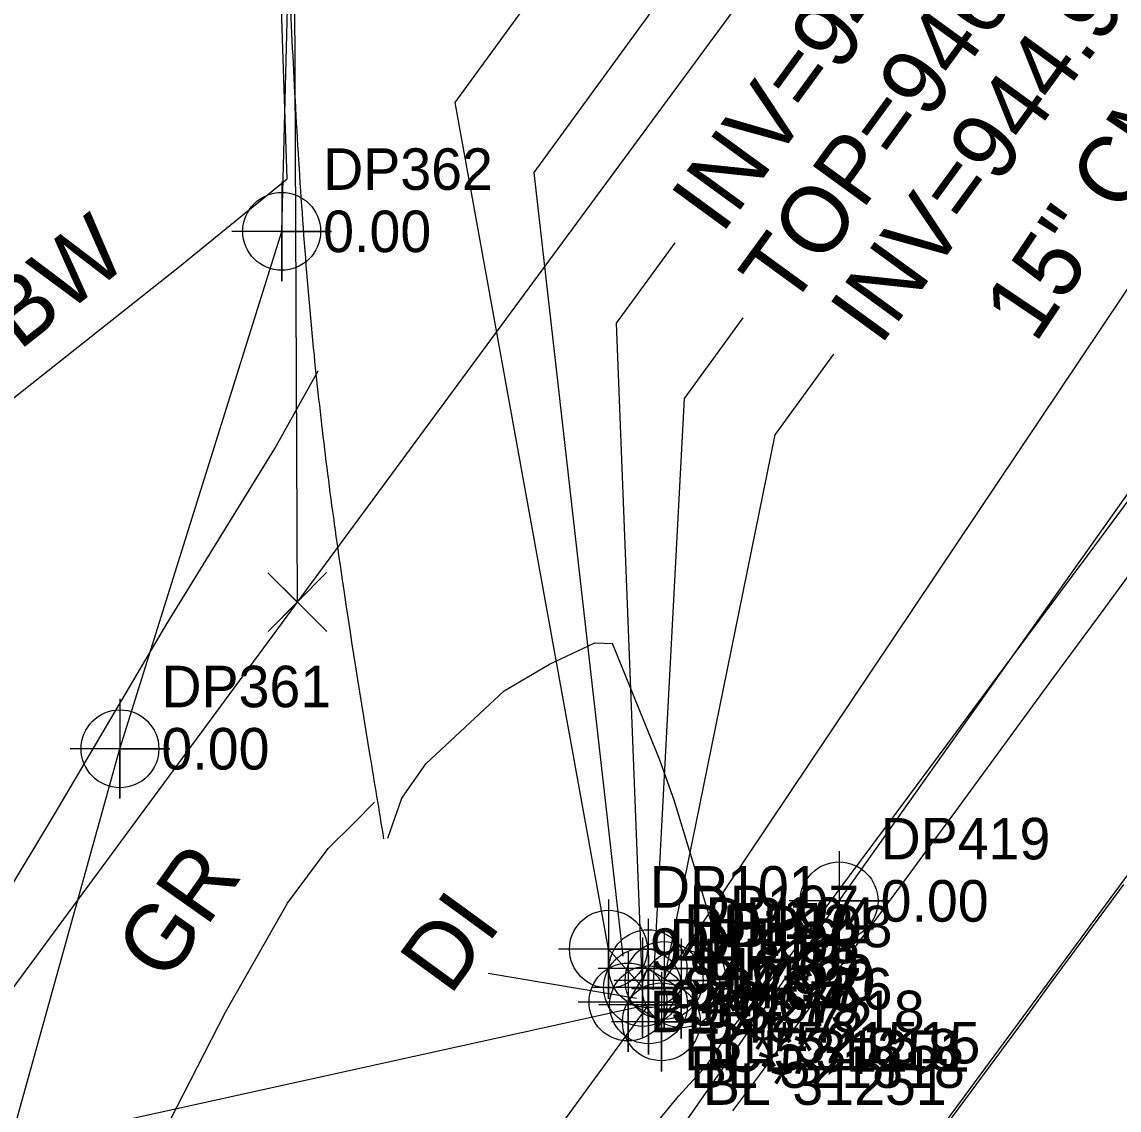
# Model space of a CAD drawing. Extents: x 1182322 to 1186765, y 572295 to 575411.
# Drawn here: x 1183866.3 to 1183932.4, y 573218.4 to 573283.9 of the extents above; entities that cross this region are included whole.
import ezdxf

# ---------------------------------------------------------------- set-up
doc = ezdxf.new("R2010")
doc.units = 0
for name, color, linetype in [('COGO Default Chain', 7, 'Continuous'), ('Exist Horizontal Alignment', 7, 'Continuous'), ('Exist Other Culture Fence Line', 7, 'Continuous'), ('Exist Other Culture Fence Line Text', 7, 'Continuous'), ('Exist Property Corner CELL', 7, 'Continuous'), ('Exist Property Line', 7, 'Continuous'), ('Exist Right of Way Line', 7, 'Continuous'), ('Exist Roads EOP', 7, 'Continuous'), ('Exist Roads EOP Other', 7, 'Continuous'), ('Exist Roads EOT', 7, 'Continuous'), ('Exist Roads Soil', 7, 'Continuous'), ('Exist Roads Soil Text', 7, 'Continuous'), ('Exist Structure Minor Drop Inlet', 7, 'Continuous'), ('Exist Structure Minor Drop Inlet Cogo Comment', 7, 'Continuous'), ('Exist Structure Minor Drop Inlet Cogo Elevation', 7, 'Continuous'), ('Exist Structure Minor Drop Inlet Cogo Number', 7, 'Continuous'), ('Exist Structure Minor Drop Inlet Cogo Point CELL', 7, 'Continuous'), ('Exist Structure Minor Drop Inlet Leader', 7, 'Continuous'), ('Exist Structure Minor Drop Inlet Text', 7, 'Continuous'), ('Exist Structure Minor Drop Inlet Top Elevation', 7, 'Continuous'), ('Exist Structure Minor Pipes CMP 15 Inch', 7, 'Continuous'), ('Exist Structure Minor Pipes CMP 15 Inch Cogo Comment', 7, 'Continuous'), ('Exist Structure Minor Pipes CMP 15 Inch Cogo Elevation', 7, 'Continuous'), ('Exist Structure Minor Pipes CMP 15 Inch Cogo Number', 7, 'Continuous'), ('Exist Structure Minor Pipes CMP 15 Inch Cogo Point CELL', 7, 'Continuous'), ('Exist Structure Minor Pipes CMP 15 Inch Invert', 7, 'Continuous'), ('Exist Structure Minor Pipes CMP 15 Inch Text', 7, 'Continuous'), ('Exist Structure Minor Pipes CMP 18 Inch', 7, 'Continuous'), ('Exist Structure Minor Pipes CMP 18 Inch Cogo Comment', 7, 'Continuous'), ('Exist Structure Minor Pipes CMP 18 Inch Cogo Elevation', 7, 'Continuous'), ('Exist Structure Minor Pipes CMP 18 Inch Cogo Number', 7, 'Continuous'), ('Exist Structure Minor Pipes CMP 18 Inch Cogo Point CELL', 7, 'Continuous'), ('Exist Structure Minor Pipes CMP 18 Inch Invert', 7, 'Continuous'), ('Exist Structure Minor Pipes CMP 18 Inch Leader', 7, 'Continuous'), ('Exist Utilities Telephone UG Cable SUE LOS C', 7, 'Continuous'), ('Exist Utilities Telephone UG Cable SUE LOS C Cogo Elevation', 7, 'Continuous'), ('Exist Utilities Telephone UG Cable SUE LOS C Cogo Number', 7, 'Continuous'), ('Exist Utilities Telephone UG Cable SUE LOS C Cogo Point CELL', 7, 'Continuous'), ('Exist Utilities Telephone UG FO SUE LOS C', 7, 'Continuous'), ('Exist Utilities Telephone UG FO SUE LOS C Cogo Elevation', 7, 'Continuous'), ('Exist Utilities Telephone UG FO SUE LOS C Cogo Number', 7, 'Continuous'), ('Exist Utilities Telephone UG FO SUE LOS C Cogo Point CELL', 7, 'Continuous')]:
    doc.layers.add(name, color=color, linetype=linetype)

msp = doc.modelspace()

# ---------------------------------------------------------------- linework, layer by layer
at = {"layer": 'COGO Default Chain'}
msp.add_line((1183822.39, 573082.624), (1183960.792, 573270.412), dxfattribs=at)
at = {"layer": 'Exist Horizontal Alignment'}
msp.add_line((1183822.39, 573082.624), (1183960.792, 573270.412), dxfattribs=at)
at = {"layer": 'Exist Other Culture Fence Line'}
for points in [[(1183875.706, 573269.13), (1183882.281, 573274.5), (1183880.264, 573335.479), (1183879.942, 573365.545), (1183879.147, 573405.433), (1183879.443, 573440.932), (1183879.29, 573466.248), (1183879.454, 573496.478), (1183879.147, 573519.038), (1183879.392, 573536.929)], [(1183822.128, 573226.748), (1183822.325, 573226.605), (1183840.399, 573241.182), (1183875.706, 573269.13)]]:
    msp.add_lwpolyline(points, dxfattribs=at)
at = {"layer": 'Exist Property Corner CELL'}
msp.add_line((1183882.9, 573249.002), (1183882.9, 573249.002), dxfattribs=at)
msp.add_lwpolyline([(1183884.675, 573247.242), (1183881.124, 573250.762), (1183882.9, 573249.002), (1183881.14, 573247.226), (1183884.66, 573250.777)], dxfattribs=at)
at = {"layer": 'Exist Property Line'}
msp.add_line((1183882.9, 573249.002), (1183880.082, 573905.178), dxfattribs=at)
at = {"layer": 'Exist Right of Way Line'}
msp.add_line((1183782.141, 573112.288), (1183920.542, 573300.076), dxfattribs=at)
at = {"layer": 'Exist Roads EOP'}
for points in [[(1183909.008, 573223.249), (1183912.581, 573227.696), (1183916.155, 573232.509), (1183919.729, 573237.324), (1183923.303, 573242.139), (1183926.878, 573246.955), (1183930.453, 573251.77), (1183934.028, 573256.586), (1183937.602, 573261.401), (1183941.177, 573266.216), (1183944.753, 573271.031), (1183948.329, 573275.845), (1183951.903, 573280.659), (1183955.478, 573285.472), (1183959.053, 573290.286), (1183962.587, 573295.131), (1183965.957, 573300.091), (1183969.392, 573305.007), (1183972.931, 573309.849), (1183975.448, 573313.161)], [(1183907.64, 573230.343), (1183905.584, 573237.076), (1183904.715, 573239.546), (1183903.781, 573241.808), (1183901.869, 573246.517)], [(1183896.313, 573204.685), (1183897.787, 573206.702), (1183899.179, 573208.776), (1183900.543, 573210.869), (1183901.682, 573213.094), (1183902.796, 573215.329), (1183904.285, 573217.335), (1183905.87, 573219.264), (1183907.547, 573221.115), (1183908.955, 573223.183), (1183908.94, 573225.671), (1183908.356, 573228.021), (1183907.646, 573230.325)]]:
    msp.add_lwpolyline(points, dxfattribs=at)
msp.add_spline([(1183888.111, 573234.75), (1183887.266, 573239.862), (1183885.398, 573251.839), (1183884.594, 573257.847), (1183883.92, 573263.875), (1183882.827, 573278.308), (1183882.139, 573292.763), (1183881.535, 573306.754), (1183881.086, 573320.75), (1183880.571, 573351.991), (1183880.026, 573376.469)], degree=3, dxfattribs=at)
at = {"layer": 'Exist Roads EOP Other'}
msp.add_lwpolyline([(1183888.336, 573234.788), (1183889.189, 573237.205), (1183890.64, 573239.26), (1183895.356, 573243.663), (1183898.082, 573245.264), (1183900.819, 573246.558), (1183901.869, 573246.517)], dxfattribs=at)
at = {"layer": 'Exist Roads EOT'}
for points in [[(1183909.126, 573218.371), (1183910.622, 573220.373), (1183912.117, 573222.374), (1183913.611, 573224.375), (1183915.107, 573226.377), (1183916.602, 573228.378), (1183918.097, 573230.38), (1183919.589, 573232.386), (1183921.066, 573234.399), (1183922.544, 573236.415), (1183924.021, 573238.43), (1183925.498, 573240.446), (1183926.977, 573242.46), (1183928.457, 573244.474), (1183929.938, 573246.487), (1183931.418, 573248.5), (1183932.898, 573250.514)], [(1183922.291, 573217.923), (1183923.777, 573219.931), (1183925.261, 573221.942), (1183926.741, 573223.954), (1183928.222, 573225.967), (1183929.703, 573227.98), (1183931.184, 573229.993), (1183932.664, 573232.006)]]:
    msp.add_lwpolyline(points, dxfattribs=at)
at = {"layer": 'Exist Roads Soil'}
for points in [[(1183755.873, 573330.816), (1183765.138, 573309.872), (1183771.686, 573295.329), (1183780.035, 573281.755), (1183791.891, 573260.841), (1183800.45, 573245.847), (1183810.819, 573229.111), (1183816.525, 573221.117), (1183823.782, 573213.839), (1183828.634, 573210.3), (1183831.855, 573208.707), (1183837.122, 573206.804), (1183840.935, 573206.353), (1183842.977, 573206.546), (1183844.891, 573206.932), (1183846.712, 573207.652), (1183848.009, 573208.384), (1183849.32, 573209.506), (1183856.494, 573218.373), (1183862.168, 573226.089), (1183868.28, 573236.258), (1183875.04, 573247.694), (1183881.535, 573258.254), (1183884.151, 573262.938)], [(1183893.801, 573201.366), (1183889.036, 573197.634), (1183886.486, 573196.138), (1183879.339, 573192.758), (1183875.323, 573191.588), (1183870.883, 573191.124), (1183867.11, 573191.214), (1183865.739, 573191.904), (1183864.44, 573193.109), (1183864.328, 573193.924), (1183864.577, 573195.747), (1183866.17, 573198.968), (1183873.534, 573214.473), (1183878.575, 573224.315), (1183882.305, 573230.864), (1183884.757, 573234.166), (1183886.379, 573235.764), (1183887.543, 573236.959)]]:
    msp.add_lwpolyline(points, dxfattribs=at)
at = {"layer": 'Exist Structure Minor Drop Inlet'}
msp.add_lwpolyline([(1183904.82, 573223.726), (1183902.81, 573224.92), (1183904.015, 573226.93), (1183906.014, 573225.717), (1183904.82, 573223.726)], dxfattribs=at)
at = {"layer": 'Exist Structure Minor Drop Inlet Cogo Point CELL'}
for points in [[(1183904.015, 573229.93), (1183904.015, 573223.93), (1183904.015, 573226.93), (1183907.015, 573226.93), (1183901.015, 573226.93)], [(1183906.014, 573228.717), (1183906.014, 573222.717), (1183906.014, 573225.717), (1183909.014, 573225.717), (1183903.014, 573225.717)], [(1183902.81, 573227.92), (1183902.81, 573221.92), (1183902.81, 573224.92), (1183905.81, 573224.92), (1183899.81, 573224.92)], [(1183904.82, 573226.726), (1183904.82, 573220.726), (1183904.82, 573223.726), (1183907.82, 573223.726), (1183901.82, 573223.726)]]:
    msp.add_lwpolyline(points, dxfattribs=at)
for centre in [(1183904.015, 573226.93), (1183906.014, 573225.717), (1183902.81, 573224.92), (1183904.82, 573223.726)]:
    msp.add_circle(centre, 2.344, dxfattribs=at)
at = {"layer": 'Exist Structure Minor Drop Inlet Leader'}
msp.add_line((1183903.311, 573225.13), (1183894.39, 573226.64), dxfattribs=at)
at = {"layer": 'Exist Structure Minor Pipes CMP 15 Inch'}
msp.add_line((1183904.982, 573226.217), (1183966.819, 573318.499), dxfattribs=at)
at = {"layer": 'Exist Structure Minor Pipes CMP 15 Inch Cogo Point CELL'}
msp.add_lwpolyline([(1183904.982, 573229.217), (1183904.982, 573223.217), (1183904.982, 573226.217), (1183907.982, 573226.217), (1183901.982, 573226.217)], dxfattribs=at)
msp.add_circle((1183904.982, 573226.217), 2.344, dxfattribs=at)
at = {"layer": 'Exist Structure Minor Pipes CMP 18 Inch'}
for p, q in [((1183901.63, 573228.102), (1183903.684, 573225.798)), ((1183904.046, 573224.75), (1183807.68, 573092.895))]:
    msp.add_line(p, q, dxfattribs=at)
at = {"layer": 'Exist Structure Minor Pipes CMP 18 Inch Cogo Point CELL'}
for points in [[(1183901.63, 573231.102), (1183901.63, 573225.102), (1183901.63, 573228.102), (1183904.63, 573228.102), (1183898.63, 573228.102)], [(1183903.684, 573228.798), (1183903.684, 573222.798), (1183903.684, 573225.798), (1183906.684, 573225.798), (1183900.684, 573225.798)], [(1183904.046, 573227.75), (1183904.046, 573221.75), (1183904.046, 573224.75), (1183907.046, 573224.75), (1183901.046, 573224.75)]]:
    msp.add_lwpolyline(points, dxfattribs=at)
for centre in [(1183901.63, 573228.102), (1183903.684, 573225.798), (1183904.046, 573224.75)]:
    msp.add_circle(centre, 2.344, dxfattribs=at)
at = {"layer": 'Exist Structure Minor Pipes CMP 18 Inch Invert'}
for points in [[(1183902.516, 573227.677), (1183897.149, 573274.868), (1183912.997, 573296.612)], [(1183901.63, 573228.102), (1183892.395, 573279.102), (1183904.279, 573295.408)], [(1183903.684, 573225.798), (1183902.113, 573265.795), (1183905.647, 573270.644)], [(1183904.315, 573225.644), (1183906.215, 573261.271), (1183909.748, 573266.12)], [(1183904.982, 573226.217), (1183911.664, 573259.079), (1183915.198, 573263.928)]]:
    msp.add_lwpolyline(points, dxfattribs=at)
at = {"layer": 'Exist Structure Minor Pipes CMP 18 Inch Leader'}
msp.add_lwpolyline([(1183904.046, 573224.75), (1183864.063, 573215.935), (1183860.529, 573211.086)], dxfattribs=at)
at = {"layer": 'Exist Utilities Telephone UG Cable SUE LOS C'}
msp.add_lwpolyline([(1183761.253, 573038.534), (1183769.092, 573034.408), (1183772.833, 573037.903), (1183792.842, 573062.439), (1183815.503, 573091.515), (1183842.15, 573128.304), (1183871.653, 573168.112), (1183894.449, 573200.637), (1183915.523, 573231.01), (1183941.953, 573268.282), (1183966.784, 573306.066), (1183979.43, 573323.536), (1183993.988, 573342.832), (1184020.646, 573379.958), (1184047.466, 573417.15), (1184074.681, 573455.299), (1184101.327, 573490.896), (1184089.429, 573505.284)], dxfattribs=at)
at = {"layer": 'Exist Utilities Telephone UG Cable SUE LOS C Cogo Point CELL'}
msp.add_lwpolyline([(1183915.523, 573234.01), (1183915.523, 573228.01), (1183915.523, 573231.01), (1183918.523, 573231.01), (1183912.523, 573231.01)], dxfattribs=at)
msp.add_circle((1183915.523, 573231.01), 2.344, dxfattribs=at)
at = {"layer": 'Exist Utilities Telephone UG FO SUE LOS C'}
msp.add_lwpolyline([(1183831.197, 573051.404), (1183831.988, 573067.671), (1183835.941, 573100.343), (1183843.81, 573135.412), (1183849.422, 573158.282), (1183872.211, 573240.171), (1183881.951, 573271.332), (1183882.592, 573295.878), (1183881.953, 573329.75), (1183881.173, 573370.193), (1183880.739, 573416.085), (1183881.105, 573461.728), (1183880.375, 573505.494), (1183880.228, 573551.998), (1183881.563, 573597.965), (1183880.769, 573642.039), (1183880.144, 573689.544)], dxfattribs=at)
at = {"layer": 'Exist Utilities Telephone UG FO SUE LOS C Cogo Point CELL'}
for points in [[(1183881.951, 573274.332), (1183881.951, 573268.332), (1183881.951, 573271.332), (1183884.951, 573271.332), (1183878.951, 573271.332)], [(1183872.211, 573243.171), (1183872.211, 573237.171), (1183872.211, 573240.171), (1183875.211, 573240.171), (1183869.211, 573240.171)]]:
    msp.add_lwpolyline(points, dxfattribs=at)
for centre in [(1183881.951, 573271.332), (1183872.211, 573240.171)]:
    msp.add_circle(centre, 2.344, dxfattribs=at)

# ---------------------------------------------------------------- texts
at = {"layer": 'Exist Other Culture Fence Line Text'}
msp.add_text('72" CHL W/3SBW', height=4, rotation=38.36348, dxfattribs=at).set_placement((1183839.01, 573242.633))
at = {"layer": 'Exist Roads Soil Text'}
msp.add_text('GR', height=4, rotation=54.86107, dxfattribs=at).set_placement((1183875.015, 573225.974))
at = {"layer": 'Exist Structure Minor Drop Inlet Cogo Comment'}
for s, p in [('CL*31251', (1183908.514, 573220.717)), ('BL*31251', (1183907.32, 573218.726))]:
    msp.add_text(s, height=2.5, dxfattribs=at).set_placement(p)
at = {"layer": 'Exist Structure Minor Drop Inlet Cogo Elevation'}
for s, p in [('946.69', (1183906.515, 573225.68)), ('946.76', (1183908.514, 573224.467)), ('946.67', (1183905.31, 573223.67)), ('946.72', (1183907.32, 573222.476))]:
    msp.add_text(s, height=2.5, dxfattribs=at).set_placement(p)
at = {"layer": 'Exist Structure Minor Drop Inlet Cogo Number'}
for s, p in [('DP107', (1183906.515, 573229.43)), ('DP108', (1183908.514, 573228.217)), ('DP106', (1183905.31, 573227.42)), ('DP105', (1183907.32, 573226.226))]:
    msp.add_text(s, height=2.5, dxfattribs=at).set_placement(p)
at = {"layer": 'Exist Structure Minor Drop Inlet Text'}
msp.add_text('DI', height=4, rotation=53.91567, dxfattribs=at).set_placement((1183892.088, 573225.23))
at = {"layer": 'Exist Structure Minor Drop Inlet Top Elevation'}
msp.add_text("TOP=946.67'", height=4, rotation=53.91567, dxfattribs=at).set_placement((1183912.543, 573266.559))
at = {"layer": 'Exist Structure Minor Pipes CMP 15 Inch Cogo Comment'}
msp.add_text('BL*521515', height=2.5, dxfattribs=at).set_placement((1183907.482, 573221.217))
at = {"layer": 'Exist Structure Minor Pipes CMP 15 Inch Cogo Elevation'}
msp.add_text('944.90', height=2.5, dxfattribs=at).set_placement((1183907.482, 573224.967))
at = {"layer": 'Exist Structure Minor Pipes CMP 15 Inch Cogo Number'}
msp.add_text('DP104', height=2.5, dxfattribs=at).set_placement((1183907.482, 573228.717))
at = {"layer": 'Exist Structure Minor Pipes CMP 15 Inch Invert'}
msp.add_text("INV=944.90'", height=4, rotation=53.91567, dxfattribs=at).set_placement((1183917.993, 573264.366))
at = {"layer": 'Exist Structure Minor Pipes CMP 15 Inch Text'}
msp.add_text('15" CMP', height=4, rotation=56.17455, dxfattribs=at).set_placement((1183927.336, 573264.518))
at = {"layer": 'Exist Structure Minor Pipes CMP 18 Inch Cogo Comment'}
for s, p in [('BL*521818', (1183904.13, 573223.102)), ('EL*521818', (1183906.184, 573220.798)), ('BL*521818', (1183906.546, 573219.75))]:
    msp.add_text(s, height=2.5, dxfattribs=at).set_placement(p)
at = {"layer": 'Exist Structure Minor Pipes CMP 18 Inch Cogo Elevation'}
for s, p in [('944.92', (1183904.13, 573226.852)), ('944.92', (1183906.184, 573224.548)), ('944.79', (1183906.546, 573223.5))]:
    msp.add_text(s, height=2.5, dxfattribs=at).set_placement(p)
at = {"layer": 'Exist Structure Minor Pipes CMP 18 Inch Cogo Number'}
for s, p in [('DP101', (1183904.13, 573230.602)), ('DP102', (1183906.184, 573228.298)), ('DP103', (1183906.546, 573227.25))]:
    msp.add_text(s, height=2.5, dxfattribs=at).set_placement(p)
at = {"layer": 'Exist Structure Minor Pipes CMP 18 Inch Invert'}
msp.add_text("INV=944.92'", height=4, rotation=53.91567, dxfattribs=at).set_placement((1183908.441, 573271.082))
at = {"layer": 'Exist Utilities Telephone UG Cable SUE LOS C Cogo Elevation'}
msp.add_text('0.00', height=2.5, dxfattribs=at).set_placement((1183918.023, 573229.76))
at = {"layer": 'Exist Utilities Telephone UG Cable SUE LOS C Cogo Number'}
msp.add_text('DP419', height=2.5, dxfattribs=at).set_placement((1183918.023, 573233.51))
at = {"layer": 'Exist Utilities Telephone UG FO SUE LOS C Cogo Elevation'}
for p in [(1183884.451, 573270.082), (1183874.711, 573238.921)]:
    msp.add_text('0.00', height=2.5, dxfattribs=at).set_placement(p)
at = {"layer": 'Exist Utilities Telephone UG FO SUE LOS C Cogo Number'}
for s, p in [('DP362', (1183884.451, 573273.832)), ('DP361', (1183874.711, 573242.671))]:
    msp.add_text(s, height=2.5, dxfattribs=at).set_placement(p)

doc.saveas('drawing.dxf')
